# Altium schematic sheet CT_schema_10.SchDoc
size 274 x 160 mm
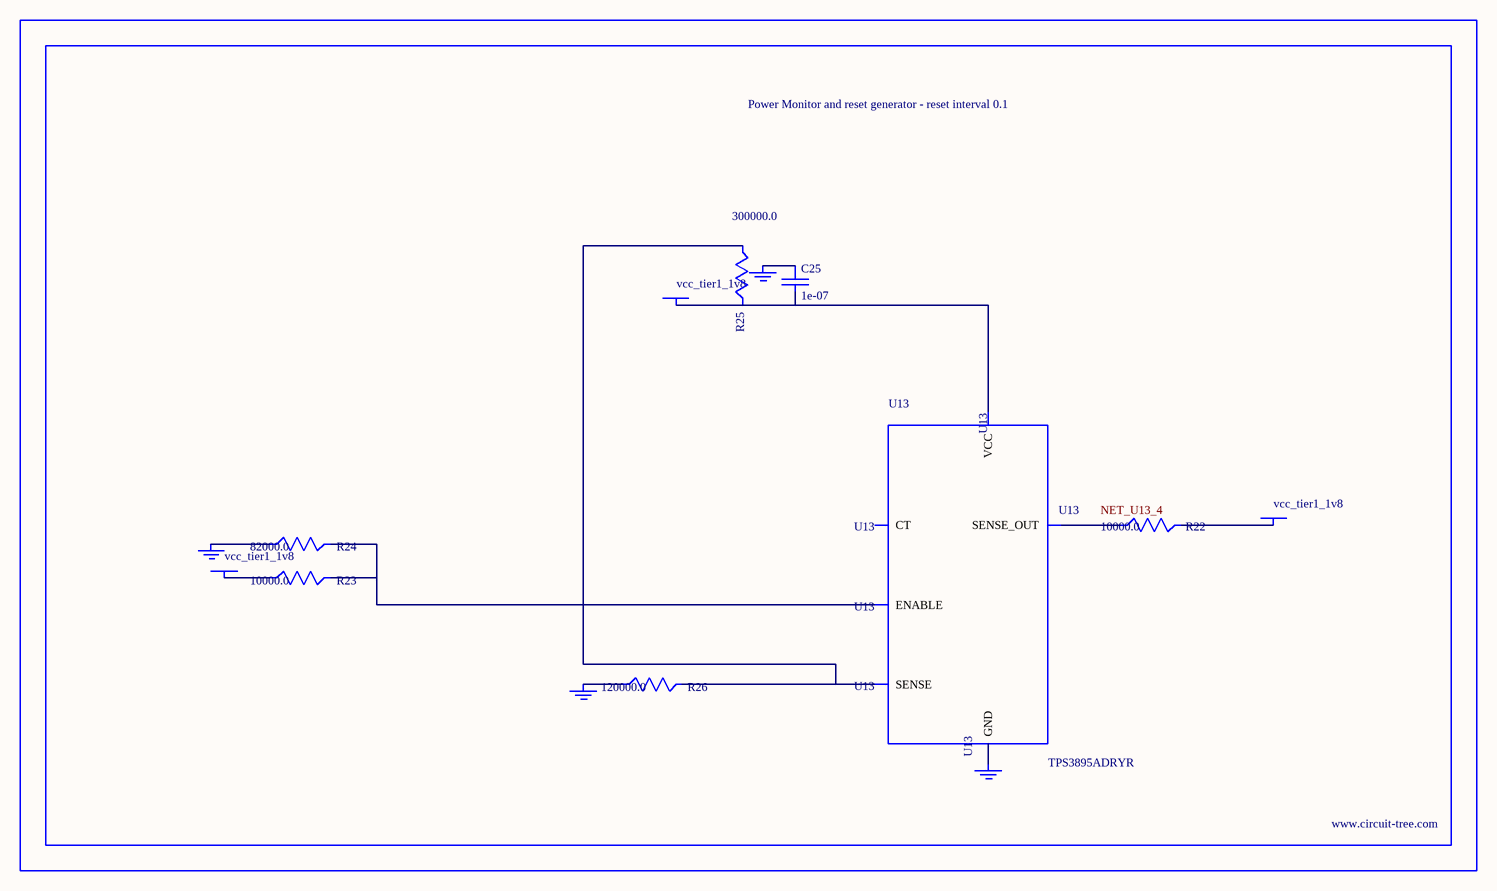
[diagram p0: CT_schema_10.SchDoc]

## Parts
BORDER9  (no value)
C25  1e-07  [C0402]
GND_INSTANCE_9_0  (no value)
GND_INSTANCE_9_1  (no value)
GND_INSTANCE_9_2  (no value)
GND_INSTANCE_9_3  (no value)
POWER_INSTANCE_9_0  vcc_tier1_1v8
POWER_INSTANCE_9_1  vcc_tier1_1v8
POWER_INSTANCE_9_2  vcc_tier1_1v8
R22  10000.0  [R0603]
R23  10000.0  [R0603]
R24  82000.0  [R0603]
R25  300000.0  [R0603]
R26  120000.0  [R0603]
U13  TPS3895ADRYR  [SON-6]

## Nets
NetC25_1: C25.1 GND_INSTANCE_9_2.0(GND)
NetC25_2: C25.2 POWER_INSTANCE_9_2.0(PWR) R25.2 U13.6(VCC)
NetGND_INSTANCE_9_0_0: GND_INSTANCE_9_0.0(GND) R24.1
NetGND_INSTANCE_9_1_0: GND_INSTANCE_9_1.0(GND) R26.1
NetGND_INSTANCE_9_3_0: GND_INSTANCE_9_3.0(GND) U13.2(GND)
NetPOWER_INSTANCE_9_0_0: POWER_INSTANCE_9_0.0(PWR) R23.1
NetPOWER_INSTANCE_9_1_0: POWER_INSTANCE_9_1.0(PWR) R22.2
NetR22_1: R22.1 U13.4(SENSE_OUT)
NetR23_2: R23.2 R24.2 U13.1(ENABLE)
NetR25_1: R25.1 R26.2 U13.3(SENSE)

Not connected (* = marked no-connect by the designer): U13 5(CT)

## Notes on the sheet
- Labels drawn without touching a wire or pin: NET_U13_4

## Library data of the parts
BORDER9 = BORDER_PAGE9
C25 = C0402C104K3RACTU
GND_INSTANCE_9_0-GND_INSTANCE_9_3 = GND
POWER_INSTANCE_9_0-POWER_INSTANCE_9_2 = PWR
R22 R23 = RC0603JR-0710KL
R24 = RC0603JR-0782KL
R25 = RC0603JR-07300KL
R26 = RC0603JR-07120KL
